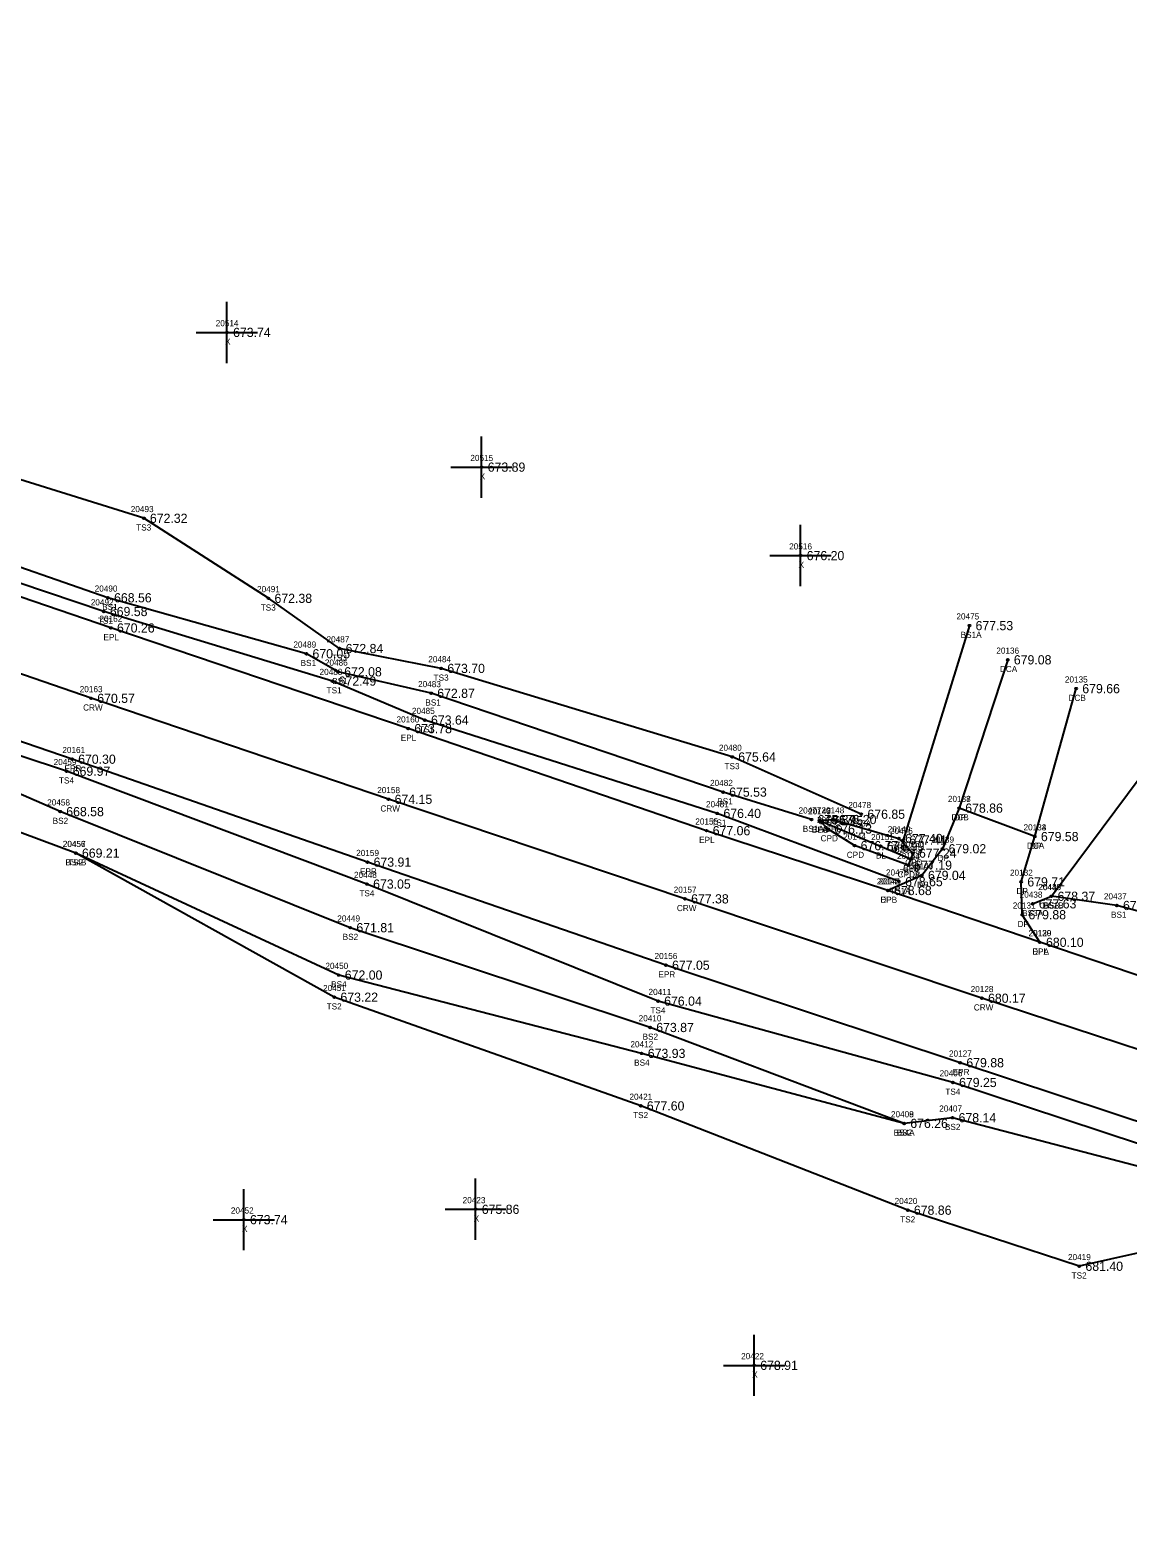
# Model space of a CAD drawing. Extents: x 1655675 to 1657082, y 1004080 to 1005193.
# Drawn here: x 1656661.8 to 1656840.9, y 1004388.9 to 1004634.8 of the extents above; entities that cross this region are included whole.
import ezdxf

# ---------------------------------------------------------------- set-up
doc = ezdxf.new("R2010")
doc.units = 0
for name, color, linetype in [('RD_DTM_BkLn1', 7, 'Continuous'), ('RD_DTM_BkLn2', 7, 'Continuous'), ('RD_DTM_BkLn_txCode', 7, 'Continuous'), ('RD_EX_Conc', 7, 'Continuous'), ('RD_EX_Conc_txCode', 7, 'Continuous'), ('RD_EX_Driveway', 7, 'Continuous'), ('RD_EX_Driveway_txCode', 7, 'Continuous'), ('RD_EX_Misc', 7, 'Continuous'), ('RD_EX_Misc_txCode', 7, 'Continuous'), ('RD_EX_Road', 7, 'Continuous'), ('RD_EX_Road_txCode', 7, 'Continuous'), ('RD_EX_TX_Conc_ELEV', 7, 'Continuous'), ('RD_EX_TX_Driveway_ELEV', 7, 'Continuous'), ('RD_EX_TX_Misc_ELEV', 7, 'Continuous'), ('RD_EX_TX_Road_ELEV', 7, 'Continuous'), ('RD_HC_Survey_ELEV', 7, 'Continuous'), ('RD_HC_Survey_txCode', 7, 'Continuous'), ('RD_SMD_Locator', 7, 'Continuous')]:
    doc.layers.add(name, color=color, linetype=linetype)

msp = doc.modelspace()

# ---------------------------------------------------------------- linework, layer by layer
at = {"layer": 'RD_DTM_BkLn1'}
for points in [[(1657061.44, 1004399.53), (1657012.07, 1004414.01), (1656963.11, 1004429.39), (1656914.21, 1004444.93), (1656865.73, 1004460.97), (1656817.07, 1004476.94), (1656768.62, 1004493.15), (1656720.24, 1004509.39), (1656671.72, 1004525.86), (1656623.45, 1004542.51), (1656574.61, 1004558.72), (1656526.43, 1004574.41), (1656478.09, 1004590.75), (1656429.6, 1004607.09), (1656401.58, 1004616.48)], [(1656790.55, 1004505.94), (1656800.54, 1004501.73), (1656805.46, 1004499.66)]]:
    msp.add_lwpolyline(points, dxfattribs=at)
at = {"layer": 'RD_DTM_BkLn2'}
msp.add_line((1656815.03, 1004537.72), (1656804.21, 1004502.74), dxfattribs=at)
for points in [[(1656797.39, 1004506.96), (1656776.31, 1004516.3), (1656728.84, 1004530.74), (1656712.25, 1004533.98), (1656700.64, 1004542.17), (1656680.31, 1004555.23), (1656632.99, 1004569.98), (1656586.53, 1004592.18), (1656570.04, 1004598.13), (1656574.64, 1004634.85)], [(1656803.54, 1004495.96), (1656773.89, 1004507.09), (1656726.18, 1004522.31), (1656711.1, 1004528.67), (1656673.78, 1004540.02), (1656627.76, 1004555.5), (1656580.25, 1004570.71), (1656563.44, 1004578.65), (1656561.74, 1004584.99)], [(1656789.27, 1004506.07), (1656774.83, 1004510.56), (1656727.19, 1004526.68), (1656712.01, 1004530.19), (1656706.84, 1004533.13), (1656674.46, 1004542.26), (1656628.8, 1004558.14), (1656594.97, 1004570.17), (1656581.6, 1004574.02), (1656564.13, 1004580.94)], [(1656916.22, 1004427.16), (1656860.73, 1004444.79), (1656812.26, 1004457.45), (1656804.38, 1004456.52), (1656762.93, 1004472.17), (1656714, 1004488.45), (1656666.66, 1004507.38), (1656620.12, 1004527.68), (1656568.41, 1004543.92), (1656526.96, 1004552.22)], [(1656917.58, 1004430.1), (1656861.23, 1004447.04), (1656812.34, 1004463.2), (1656764.22, 1004476.47), (1656716.73, 1004495.56), (1656667.72, 1004513.97), (1656620.99, 1004529.43), (1656569.32, 1004546.11), (1656560.19, 1004551.77)], [(1656877.14, 1004434.43), (1656862.63, 1004439.86), (1656832.96, 1004433.22), (1656804.97, 1004442.37), (1656761.39, 1004459.38), (1656711.4, 1004477.11), (1656669.22, 1004500.61), (1656617.04, 1004520), (1656542.14, 1004544.84), (1656525.4, 1004509.94)], [(1656825.35, 1004492.34), (1656828.41, 1004493.57), (1656842.91, 1004513.01), (1656853.69, 1004530.7)], [(1656804.38, 1004456.52), (1656761.55, 1004467.94), (1656712.11, 1004480.72), (1656669.22, 1004500.61)], [(1657053.5, 1004416.94), (1657016.16, 1004427.41), (1656967.32, 1004443.62), (1656919.43, 1004460.12), (1656872.94, 1004483.02), (1656839.09, 1004492.07), (1656828.41, 1004493.57)]]:
    msp.add_lwpolyline(points, dxfattribs=at)
at = {"layer": 'RD_EX_Conc'}
for p, q in [((1656821.28, 1004532.14), (1656813.35, 1004507.95)), ((1656825.7, 1004503.31), (1656832.45, 1004527.44))]:
    msp.add_line(p, q, dxfattribs=at)
msp.add_lwpolyline([(1656805.05, 1004498.64), (1656796.28, 1004501.83), (1656792, 1004504.53), (1656790.55, 1004505.94), (1656792.73, 1004506.09), (1656803.53, 1004503), (1656805.8, 1004500.61), (1656805.46, 1004499.66), (1656805.05, 1004498.64)], dxfattribs=at)
at = {"layer": 'RD_EX_Driveway'}
msp.add_lwpolyline([(1656826.53, 1004486.06), (1656823.66, 1004490.56), (1656823.48, 1004495.92), (1656825.7, 1004503.31), (1656813.35, 1004507.95), (1656810.63, 1004501.32), (1656807.27, 1004496.98), (1656801.74, 1004494.51)], dxfattribs=at)
at = {"layer": 'RD_EX_Misc'}
for p, q in [((1656693.88, 1004580.55), (1656693.88, 1004590.55)), ((1656688.88, 1004585.55), (1656698.88, 1004585.55)), ((1656735.43, 1004558.57), (1656735.43, 1004568.57)), ((1656730.43, 1004563.57), (1656740.43, 1004563.57)), ((1656787.48, 1004544.14), (1656787.48, 1004554.14)), ((1656782.48, 1004549.14), (1656792.48, 1004549.14)), ((1656734.46, 1004437.51), (1656734.46, 1004447.51)), ((1656696.64, 1004435.82), (1656696.64, 1004445.82)), ((1656729.46, 1004442.51), (1656739.46, 1004442.51)), ((1656691.64, 1004440.82), (1656701.64, 1004440.82)), ((1656779.9, 1004412.06), (1656779.9, 1004422.06)), ((1656774.9, 1004417.06), (1656784.9, 1004417.06))]:
    msp.add_line(p, q, dxfattribs=at)
at = {"layer": 'RD_EX_Road'}
for points in [[(1657064.39, 1004409.09), (1657015.67, 1004424.64), (1656965.82, 1004440.6), (1656917.99, 1004455.95), (1656868.5, 1004471.86), (1656826.53, 1004486.06), (1656801.74, 1004494.51), (1656772.14, 1004504.27), (1656723.45, 1004520.92), (1656674.94, 1004537.34), (1656626.5, 1004553.88), (1656578.27, 1004569.52), (1656529.18, 1004584.75), (1656481.5, 1004600.51), (1656432.67, 1004617.14), (1656404.34, 1004625.82)], [(1657057.77, 1004388.92), (1657009.7, 1004404.08), (1656958.18, 1004419.84), (1656956.49, 1004419.67), (1656924.83, 1004429.55), (1656916.51, 1004432.8), (1656911.19, 1004434.68), (1656862.46, 1004450.21), (1656813.53, 1004466.42), (1656765.51, 1004482.33), (1656716.81, 1004499.14), (1656668.6, 1004515.93), (1656620.24, 1004532.54), (1656571.72, 1004548.37), (1656523.3, 1004563.77), (1656474.37, 1004580.29), (1656426.43, 1004596.82), (1656398.22, 1004606.78)]]:
    msp.add_lwpolyline(points, dxfattribs=at)
at = {"layer": 'RD_SMD_Locator'}
for centre in [(1656693.88, 1004585.55), (1656735.43, 1004563.57), (1656680.31, 1004555.23), (1656787.48, 1004549.14), (1656674.46, 1004542.26), (1656700.64, 1004542.17), (1656673.78, 1004540.02), (1656674.94, 1004537.34), (1656815.03, 1004537.72), (1656706.84, 1004533.13), (1656712.25, 1004533.98), (1656728.84, 1004530.74), (1656821.28, 1004532.14), (1656711.1, 1004528.67), (1656712.01, 1004530.19), (1656671.72, 1004525.86), (1656727.19, 1004526.68), (1656832.45, 1004527.44), (1656723.45, 1004520.92), (1656726.18, 1004522.31), (1656668.6, 1004515.93), (1656776.31, 1004516.3), (1656667.72, 1004513.97), (1656720.24, 1004509.39), (1656774.83, 1004510.56), (1656666.66, 1004507.38), (1656773.89, 1004507.09), (1656789.27, 1004506.07), (1656790.55, 1004505.94), (1656790.55, 1004505.94), (1656792.73, 1004506.09), (1656797.39, 1004506.96), (1656813.35, 1004507.95), (1656813.35, 1004507.95), (1656772.14, 1004504.27), (1656792, 1004504.53), (1656796.28, 1004501.83), (1656800.54, 1004501.73), (1656803.53, 1004503), (1656804.21, 1004502.74), (1656810.63, 1004501.32), (1656825.7, 1004503.31), (1656825.7, 1004503.31), (1656669.22, 1004500.61), (1656669.22, 1004500.61), (1656716.81, 1004499.14), (1656805.05, 1004498.64), (1656805.05, 1004498.64), (1656805.46, 1004499.66), (1656805.46, 1004499.66), (1656805.8, 1004500.61), (1656807.27, 1004496.98), (1656716.73, 1004495.56), (1656801.74, 1004494.51), (1656801.74, 1004494.51), (1656803.54, 1004495.96), (1656823.48, 1004495.92), (1656768.62, 1004493.15), (1656825.35, 1004492.34), (1656828.41, 1004493.57), (1656828.41, 1004493.57), (1656839.09, 1004492.07), (1656823.66, 1004490.56), (1656714, 1004488.45), (1656826.53, 1004486.06), (1656826.53, 1004486.06), (1656765.51, 1004482.33), (1656712.11, 1004480.72), (1656711.4, 1004477.11), (1656764.22, 1004476.47), (1656817.07, 1004476.94), (1656762.93, 1004472.17), (1656761.55, 1004467.94), (1656813.53, 1004466.42), (1656812.34, 1004463.2), (1656761.39, 1004459.38), (1656812.26, 1004457.45), (1656804.38, 1004456.52), (1656804.38, 1004456.52), (1656734.46, 1004442.51), (1656804.97, 1004442.37), (1656696.64, 1004440.82), (1656832.96, 1004433.22), (1656779.9, 1004417.06)]:
    msp.add_circle(centre, 0.15, dxfattribs=at)

# ---------------------------------------------------------------- texts
at = {"layer": 'RD_DTM_BkLn_txCode'}
for s, p in [('20493', (1656678.19, 1004556.23)), ('TS3', (1656679.07, 1004553.23)), ('20490', (1656672.3, 1004543.26)), ('20491', (1656698.8, 1004543.17)), ('20492', (1656671.66, 1004541.02)), ('BS1', (1656673.52, 1004540.26)), ('TS3', (1656699.39, 1004540.17)), ('TS1', (1656672.82, 1004538.02)), ('20475', (1656812.91, 1004538.72)), ('20487', (1656710.13, 1004534.98)), ('BS1A', (1656813.6, 1004535.72)), ('20489', (1656704.72, 1004534.13)), ('BS1', (1656705.9, 1004531.13)), ('20488', (1656708.99, 1004529.67)), ('20486', (1656709.86, 1004531.19)), ('TS3', (1656711, 1004531.98)), ('20484', (1656726.73, 1004531.74)), ('BS1', (1656711.06, 1004528.19)), ('20483', (1656725.07, 1004527.68)), ('TS3', (1656727.6, 1004528.74)), ('TS1', (1656710.14, 1004526.67)), ('20485', (1656724.06, 1004523.31)), ('BS1', (1656726.25, 1004524.68)), ('TS1', (1656725.21, 1004520.31)), ('20459', (1656665.6, 1004514.97)), ('20480', (1656774.16, 1004517.3)), ('TS3', (1656775.07, 1004514.3)), ('TS4', (1656666.47, 1004511.97)), ('20482', (1656772.71, 1004511.56)), ('20458', (1656664.55, 1004508.38)), ('20481', (1656772.05, 1004508.09)), ('BS1', (1656773.89, 1004508.56)), ('20478', (1656795.27, 1004507.96)), ('BS2', (1656665.44, 1004505.38)), ('TS1', (1656772.93, 1004505.09)), ('20477', (1656787.15, 1004507.07)), ('20147', (1656788.72, 1004506.94)), ('BS1A', (1656787.84, 1004504.07)), ('BLA', (1656789.31, 1004503.94)), ('TS3A', (1656795.66, 1004504.96)), ('20151', (1656798.99, 1004502.73)), ('20476', (1656802.07, 1004503.74)), ('20456', (1656667.08, 1004501.61)), ('20457', (1656667.11, 1004501.61)), ('BS1B', (1656802.79, 1004500.74)), ('20152', (1656803.62, 1004500.66)), ('BS4B', (1656667.52, 1004498.61)), ('TS2', (1656667.98, 1004498.61)), ('BL', (1656799.78, 1004499.73)), ('20448', (1656714.61, 1004496.56)), ('20479', (1656801.42, 1004496.96)), ('BLB', (1656804.23, 1004497.66)), ('TS4', (1656715.49, 1004493.56)), ('TS1A', (1656802.09, 1004493.96)), ('20438', (1656823.23, 1004493.34)), ('20440', (1656826.25, 1004494.57)), ('20439', (1656826.29, 1004494.57)), ('20437', (1656836.97, 1004493.07)), ('BS3A', (1656823.63, 1004490.34)), ('BS1B', (1656826.99, 1004491.57)), ('BS3', (1656827.18, 1004491.57)), ('20449', (1656711.88, 1004489.45)), ('BS1', (1656838.14, 1004490.07)), ('BS2', (1656712.77, 1004486.45)), ('20450', (1656709.95, 1004481.72)), ('20451', (1656709.56, 1004478.11)), ('BS4', (1656710.88, 1004478.72)), ('20411', (1656762.67, 1004477.47)), ('TS2', (1656710.15, 1004475.11)), ('20410', (1656761.06, 1004473.17)), ('TS4', (1656762.98, 1004474.47)), ('20412', (1656759.72, 1004468.94)), ('BS2', (1656761.7, 1004470.17)), ('BS4', (1656760.32, 1004465.94)), ('20406', (1656810.16, 1004464.2)), ('TS4', (1656811.1, 1004461.2)), ('20421', (1656759.56, 1004460.38)), ('20407', (1656810.1, 1004458.45)), ('TS2', (1656760.15, 1004457.38)), ('20408', (1656802.23, 1004457.52)), ('20409', (1656802.23, 1004457.52)), ('BS4A', (1656802.67, 1004454.52)), ('BS2', (1656803.16, 1004454.52)), ('BS2', (1656811.03, 1004455.45)), ('20420', (1656802.82, 1004443.37)), ('TS2', (1656803.73, 1004440.37)), ('20419', (1656831.12, 1004434.22)), ('TS2', (1656831.71, 1004431.22))]:
    msp.add_text(s, height=1, dxfattribs=at).set_placement(p)
at = {"layer": 'RD_EX_Conc_txCode'}
for s, p in [('20136', (1656819.42, 1004533.14)), ('DCA', (1656820.01, 1004530.14)), ('20135', (1656830.61, 1004528.44)), ('DCB', (1656831.2, 1004525.44)), ('20137', (1656811.52, 1004508.95)), ('20146', (1656788.69, 1004506.94)), ('20145', (1656790.17, 1004505.53)), ('20148', (1656790.89, 1004507.09)), ('DCB', (1656812.1, 1004505.95)), ('CPD', (1656789.3, 1004503.94)), ('CPD', (1656791.47, 1004504.09)), ('20144', (1656794.44, 1004502.83)), ('20149', (1656801.7, 1004504)), ('20134', (1656823.86, 1004504.31)), ('CPD', (1656790.75, 1004502.53)), ('CPD', (1656802.28, 1004501)), ('20153', (1656803.62, 1004500.66)), ('20150', (1656803.93, 1004501.61)), ('DCA', (1656824.43, 1004501.31)), ('CPD', (1656795.02, 1004499.83)), ('20143', (1656803.22, 1004499.64)), ('20154', (1656803.22, 1004499.64)), ('CPD', (1656804.55, 1004498.61)), ('CPDA', (1656803.31, 1004496.64)), ('CPDB', (1656803.33, 1004496.64)), ('CPD', (1656804.2, 1004497.66))]:
    msp.add_text(s, height=1, dxfattribs=at).set_placement(p)
at = {"layer": 'RD_EX_Driveway_txCode'}
for s, p in [('20138', (1656811.52, 1004508.95)), ('DP', (1656812.58, 1004505.95)), ('20133', (1656823.86, 1004504.31)), ('20139', (1656808.8, 1004502.32)), ('DP', (1656824.92, 1004501.31)), ('20140', (1656805.39, 1004497.98)), ('DP', (1656809.85, 1004499.32)), ('20141', (1656800.19, 1004495.51)), ('20132', (1656821.65, 1004496.92)), ('DP', (1656806.49, 1004494.98)), ('DP', (1656822.71, 1004493.92)), ('DPB', (1656800.49, 1004492.51)), ('20131', (1656822.11, 1004491.56)), ('DP', (1656822.88, 1004488.56)), ('20130', (1656824.66, 1004487.06)), ('DPA', (1656825.27, 1004484.06))]:
    msp.add_text(s, height=1, dxfattribs=at).set_placement(p)
at = {"layer": 'RD_EX_Misc_txCode'}
for s, p in [('20514', (1656692.05, 1004586.55)), ('X', (1656693.57, 1004583.55)), ('20515', (1656733.6, 1004564.57)), ('X', (1656735.12, 1004561.57)), ('20516', (1656785.62, 1004550.14)), ('X', (1656787.16, 1004547.14)), ('20452', (1656694.52, 1004441.82)), ('20423', (1656732.34, 1004443.51)), ('X', (1656696.33, 1004438.82)), ('X', (1656734.14, 1004440.51)), ('20422', (1656777.78, 1004418.06)), ('X', (1656779.58, 1004415.06))]:
    msp.add_text(s, height=1, dxfattribs=at).set_placement(p)
at = {"layer": 'RD_EX_Road_txCode'}
for s, p in [('20162', (1656673.08, 1004538.34)), ('EPL', (1656673.73, 1004535.34)), ('20160', (1656721.55, 1004521.92)), ('EPL', (1656722.24, 1004518.92)), ('20161', (1656667.02, 1004516.93)), ('EPR', (1656667.37, 1004513.93)), ('20155', (1656770.3, 1004505.27)), ('20159', (1656714.97, 1004500.14)), ('EPL', (1656770.93, 1004502.27)), ('EPR', (1656715.58, 1004497.14)), ('20142', (1656799.91, 1004495.51)), ('EPL', (1656800.54, 1004492.51)), ('20129', (1656824.7, 1004487.06)), ('20156', (1656763.65, 1004483.33)), ('EPL', (1656825.33, 1004484.06)), ('EPR', (1656764.28, 1004480.33)), ('20127', (1656811.7, 1004467.42)), ('EPR', (1656812.3, 1004464.42))]:
    msp.add_text(s, height=1, dxfattribs=at).set_placement(p)
at = {"layer": 'RD_EX_TX_Conc_ELEV'}
for s, p in [('679.08', (1656822.28, 1004531.39)), ('679.66', (1656833.45, 1004526.69)), ('678.86', (1656814.35, 1004507.2)), ('675.95', (1656791.55, 1004505.19)), ('676.20', (1656793.73, 1004505.34)), ('676.13', (1656793, 1004503.78)), ('677.40', (1656804.53, 1004502.25)), ('679.58', (1656826.7, 1004502.56)), ('676.77', (1656797.28, 1004501.08)), ('677.24', (1656806.8, 1004499.86)), ('677.19', (1656806.05, 1004497.89)), ('677.19', (1656806.05, 1004497.89)), ('677.02', (1656806.46, 1004498.91))]:
    msp.add_text(s, height=1.5, dxfattribs=at).set_placement(p)
at = {"layer": 'RD_EX_TX_Driveway_ELEV'}
for s, p in [('678.86', (1656814.35, 1004507.2)), ('679.58', (1656826.7, 1004502.56)), ('679.02', (1656811.63, 1004500.57)), ('679.04', (1656808.27, 1004496.23)), ('679.71', (1656824.48, 1004495.17)), ('678.68', (1656802.74, 1004493.76)), ('679.88', (1656824.66, 1004489.81)), ('680.10', (1656827.53, 1004485.31))]:
    msp.add_text(s, height=1.5, dxfattribs=at).set_placement(p)
at = {"layer": 'RD_EX_TX_Misc_ELEV'}
for s, p in [('673.74', (1656694.88, 1004584.8)), ('673.89', (1656736.43, 1004562.82)), ('672.32', (1656681.31, 1004554.48)), ('676.20', (1656788.48, 1004548.39)), ('668.56', (1656675.46, 1004541.51)), ('669.58', (1656674.78, 1004539.27)), ('672.38', (1656701.64, 1004541.42)), ('677.53', (1656816.03, 1004536.97)), ('670.05', (1656707.84, 1004532.38)), ('672.84', (1656713.25, 1004533.23)), ('672.08', (1656713.01, 1004529.44)), ('673.70', (1656729.84, 1004529.99)), ('672.49', (1656712.1, 1004527.92)), ('672.87', (1656728.19, 1004525.93)), ('673.64', (1656727.18, 1004521.56)), ('675.64', (1656777.31, 1004515.55)), ('669.97', (1656668.72, 1004513.22)), ('675.53', (1656775.83, 1004509.81)), ('668.58', (1656667.66, 1004506.63)), ('676.40', (1656774.89, 1004506.34)), ('675.87', (1656790.27, 1004505.32)), ('675.95', (1656791.55, 1004505.19)), ('676.85', (1656798.39, 1004506.21)), ('669.21', (1656670.22, 1004499.86)), ('669.21', (1656670.22, 1004499.86)), ('676.99', (1656801.54, 1004500.98)), ('677.41', (1656805.21, 1004501.99)), ('677.02', (1656806.46, 1004498.91)), ('673.05', (1656717.73, 1004494.81)), ('678.65', (1656804.54, 1004495.21)), ('678.37', (1656829.41, 1004492.82)), ('678.37', (1656829.41, 1004492.82)), ('677.63', (1656826.35, 1004491.59)), ('678.89', (1656840.09, 1004491.32)), ('671.81', (1656715, 1004487.7)), ('672.00', (1656713.11, 1004479.97)), ('673.22', (1656712.4, 1004476.36)), ('676.04', (1656765.22, 1004475.72)), ('673.87', (1656763.93, 1004471.42)), ('673.93', (1656762.55, 1004467.19)), ('679.25', (1656813.34, 1004462.45)), ('677.60', (1656762.39, 1004458.63)), ('676.26', (1656805.38, 1004455.77)), ('676.26', (1656805.38, 1004455.77)), ('678.14', (1656813.26, 1004456.7)), ('675.86', (1656735.46, 1004441.76)), ('678.86', (1656805.97, 1004441.62)), ('673.74', (1656697.64, 1004440.07)), ('681.40', (1656833.96, 1004432.47)), ('678.91', (1656780.9, 1004416.31))]:
    msp.add_text(s, height=1.5, dxfattribs=at).set_placement(p)
at = {"layer": 'RD_EX_TX_Road_ELEV'}
for s, p in [('670.26', (1656675.94, 1004536.59)), ('673.78', (1656724.45, 1004520.17)), ('670.30', (1656669.6, 1004515.18)), ('677.06', (1656773.14, 1004503.52)), ('673.91', (1656717.81, 1004498.39)), ('678.68', (1656802.74, 1004493.76)), ('680.10', (1656827.53, 1004485.31)), ('677.05', (1656766.51, 1004481.58)), ('679.88', (1656814.53, 1004465.67))]:
    msp.add_text(s, height=1.5, dxfattribs=at).set_placement(p)
at = {"layer": 'RD_HC_Survey_ELEV'}
for s, p in [('670.57', (1656672.72, 1004525.11)), ('674.15', (1656721.24, 1004508.64)), ('677.38', (1656769.62, 1004492.4)), ('680.17', (1656818.07, 1004476.19))]:
    msp.add_text(s, height=1.5, dxfattribs=at).set_placement(p)
at = {"layer": 'RD_HC_Survey_txCode'}
for s, p in [('20163', (1656669.86, 1004526.86)), ('CRW', (1656670.41, 1004523.86)), ('20158', (1656718.4, 1004510.39)), ('CRW', (1656718.92, 1004507.39)), ('20157', (1656766.78, 1004494.15)), ('CRW', (1656767.3, 1004491.15)), ('20128', (1656815.23, 1004477.94)), ('CRW', (1656815.75, 1004474.94))]:
    msp.add_text(s, height=1, dxfattribs=at).set_placement(p)

doc.saveas('drawing.dxf')
